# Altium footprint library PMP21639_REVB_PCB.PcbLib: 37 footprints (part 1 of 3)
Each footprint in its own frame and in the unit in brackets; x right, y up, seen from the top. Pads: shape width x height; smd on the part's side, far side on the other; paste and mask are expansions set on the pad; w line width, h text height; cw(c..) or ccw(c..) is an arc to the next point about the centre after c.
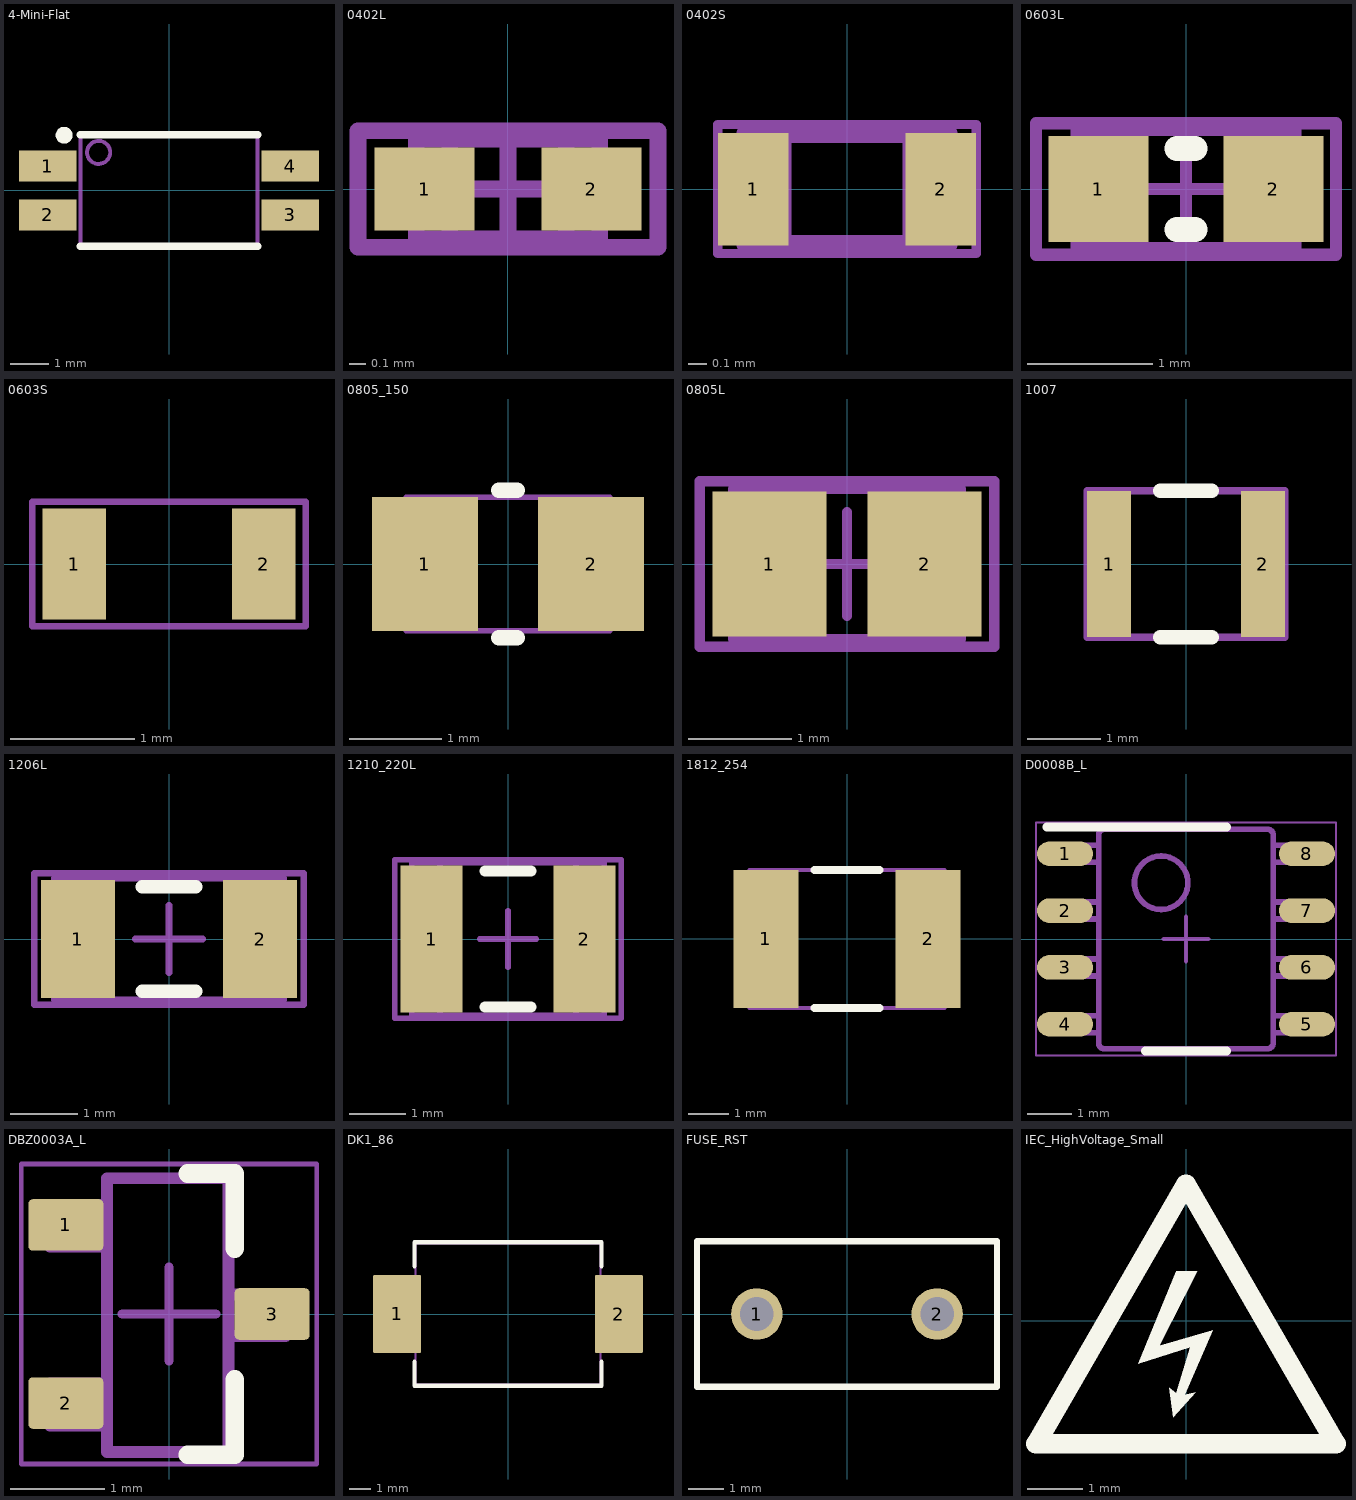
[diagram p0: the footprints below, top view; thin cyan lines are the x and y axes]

## 4-Mini-Flat [mm] "Sharp"
height 2.4
pads (4):
  rect 1.5x0.8 smd: 1(-3.15,0.635) 2(-3.15,-0.635) 3(3.15,-0.635) 4(3.15,0.635)
Top Overlay:
  circle w0.254: c-2.728,1.437 r0.091
  lines w0.2: -2.3,-1.45 2.3,-1.45 ; -2.3,1.45 2.3,1.45
Mechanical 5:
  circle w0.1: c-1.829,0.991 r0.3
  lines w0.1: -2.3,-1.45 2.3,-1.45 2.3,1.45 -2.3,1.45 -2.3,-1.45
  text ".Designator" at -1.88,-0.508 h1.02
3D body: height 2.4, standoff 0, extent -2.299,-1.449 2.3,1.45
3D body: height 2.41, standoff 2.4, extent -1.984,0.379 -1.386,0.978

## 0402L [mm] "0402 from SM-752 data"
height 0.6
pads (2):
  rect 0.6x0.5 smd: 1(-0.5,0) 2(0.5,0)
Mechanical 5:
  lines w0.1: -0.9,-0.35 0.9,-0.35 0.9,0.35 -0.9,0.35 -0.9,-0.35
  text ".Designator" at -0.775,-0.225 h0.43
Mechanical 13:
  lines w0.1: -0.35,-0.3 -0.35,0.3 ; 0.35,-0.3 0.35,0.3 ; -0.55,-0.3 -0.55,0.3 0.55,0.3 0.55,-0.3 -0.55,-0.3
Mechanical 15:
  lines w0.1: -0.3,0 0.3,0 ; 0,-0.3 0,0.3 ; -0.9,-0.35 -0.9,0.35 0.9,0.35 0.9,-0.35 -0.9,-0.35
3D body: height 0.6, standoff 0, extent -0.549,-0.299 -0.351,0.299
3D body: height 0.6, standoff 0, extent -0.349,-0.299 0.349,0.299
3D body: height 0.6, standoff 0, extent 0.351,-0.299 0.549,0.299

## 0402S [mil] "Based on C0402S footprint from PADS legacy"
height 23.62
pads (2):
  rect 15x24 smd: 1(-20,0) 2(20,0)
Mechanical 5:
  lines w1.97: -27.56,-13.78 27.56,-13.78 27.56,13.78 -27.56,13.78 -27.56,-13.78
  text ".Designator" at -21.65,-5.91 h12
Mechanical 13:
  lines w3.94: -13.78,-11.81 -13.78,11.81 ; 13.78,-11.81 13.78,11.81 ; -21.65,-11.81 -21.65,11.81 21.65,11.81 21.65,-11.81 -21.65,-11.81
3D body: height 23.62, standoff 0, extent -21.63,-11.79 -13.8,11.79
3D body: height 23.62, standoff 0, extent -13.76,-11.79 13.76,11.79
3D body: height 23.62, standoff 0, extent 13.8,-11.79 21.63,11.79

## 0603L [mm] "0603 from SM-752 data"
height 1
pads (2):
  rect 0.8x0.85 smd: 1(-0.7,0) 2(0.7,0)
Top Overlay:
  lines w0.2: -0.071,-0.325 0.071,-0.325 ; -0.071,0.325 0.071,0.325
Mechanical 5:
  lines w0.1: -1.2,-0.525 -1.2,0.525 1.2,0.525 1.2,-0.525 -1.2,-0.525
  text ".Designator" at -1.05,-0.275 h0.56
Mechanical 13:
  lines w0.1: -0.55,-0.475 -0.55,0.475 ; 0.55,-0.475 0.55,0.475 ; -0.875,-0.475 -0.875,0.475 0.875,0.475 0.875,-0.475 -0.875,-0.475
Mechanical 15:
  lines w0.1: -0.475,0 0.475,0 ; 0,-0.475 0,0.475 ; -1.2,-0.525 1.2,-0.525 1.2,0.525 -1.2,0.525 -1.2,-0.525
3D body: height 1, standoff 0, extent 0.551,-0.474 0.874,0.474
3D body: height 1, standoff 0, extent -0.549,-0.474 0.549,0.474
3D body: height 1, standoff 0, extent -0.874,-0.474 -0.551,0.474

## 0603S [mil]
height 39.37
pads (2):
  rect 20x35 smd: 1(-30,0) 2(30,0)
Mechanical 5:
  lines w1.97: -43.31,-19.68 43.31,-19.68 43.31,19.68 -43.31,19.68 -43.31,-19.68
  text ".Designator" at -32.48,-8.86 h18
3D body: height 39.37, standoff 0, extent -34.43,-18.68 -21.67,18.68
3D body: height 39.37, standoff 0, extent -21.63,-18.68 21.63,18.68
3D body: height 39.37, standoff 0, extent 21.67,-18.68 34.43,18.68

## 0805_150 [mm] "0805 / 1.5 mm height"
height 1.5
pads (2):
  rect 1.15x1.45 smd: 1(-0.9,0) 2(0.9,0)
Top Overlay:
  lines w0.17: -0.1,-0.8 0.1,-0.8 ; -0.1,0.8 0.1,0.8
Mechanical 5:
  lines w0.06: -1.1,-0.725 1.1,-0.725 1.1,0.725 -1.1,0.725 -1.1,-0.725
  text ".Designator" at -0.975,-0.3 h0.53
3D body: height 1.5, standoff 0, extent -1.099,-0.724 -0.501,0.724
3D body: height 1.5, standoff 0, extent -0.499,-0.724 0.5,0.725
3D body: height 1.5, standoff 0, extent 0.501,-0.724 1.099,0.724

## 0805L [mm] "0805 from SM-752 data"
height 1.45
pads (2):
  rect 1.1x1.4 smd: 1(-0.75,0) 2(0.75,0)
Mechanical 5:
  lines w0.1: -1.425,-0.8 1.425,-0.8 1.425,0.8 -1.425,0.8 -1.425,-0.8
  text ".Designator" at -1.2,-0.325 h0.64
Mechanical 13:
  lines w0.1: -0.65,-0.725 -0.65,0.725 ; 0.65,-0.725 0.65,0.725 ; -1.1,-0.725 -1.1,0.725 1.1,0.725 1.1,-0.725 -1.1,-0.725
Mechanical 15:
  lines w0.1: -0.5,0 0.5,0 ; 0,-0.5 0,0.5 ; -1.425,-0.8 -1.425,0.8 1.425,0.8 1.425,-0.8 -1.425,-0.8
3D body: height 1.45, standoff 0, extent 0.651,-0.724 1.099,0.724
3D body: height 1.45, standoff 0, extent -0.649,-0.724 0.649,0.724
3D body: height 1.45, standoff 0, extent -1.099,-0.724 -0.651,0.724

## 1007 [mm] "SMD, 2-Leads, Body 2.5x1.8mm"
height 2
pads (2):
  rect 0.6x2 smd: 1(-1.05,0) 2(1.05,0)
Top Overlay:
  lines w0.2: -0.35,-1 0.35,-1 ; -0.35,1 0.35,1
Mechanical 5:
  lines w0.1: -1.35,-1 1.35,-1 1.35,1 -1.35,1 -1.35,-1
  text ".Designator" at -1.1,-0.2 h0.6
3D body: height 2, standoff 0, extent 0.85,-1 1.35,1
3D body: height 2, standoff 0, extent -1.35,-1 -0.85,1
3D body: height 2, standoff 0, extent -0.85,-1 0.85,1

## 1206L [mm] "1206 from SM-752 data"
height 1.35
pads (2):
  rect 1.1x1.75 smd: 1(-1.35,0) 2(1.35,0)
Top Overlay:
  lines w0.2: -0.4,-0.775 0.4,-0.775 ; -0.4,0.775 0.4,0.775
Mechanical 5:
  lines w0.1: -1.7,-0.9 1.7,-0.9 1.7,0.9 -1.7,0.9 -1.7,-0.9
  text ".Designator" at -1.475,-0.4 h0.81
Mechanical 13:
  lines w0.1: -1.2,-0.9 -1.2,0.9 ; 1.2,-0.9 1.2,0.9 ; -1.7,-0.9 -1.7,0.9 1.7,0.9 1.7,-0.9 -1.7,-0.9
Mechanical 15:
  lines w0.1: -0.5,0 0.5,0 ; 0,-0.5 0,0.5 ; -2,-0.975 2,-0.975 2,0.975 -2,0.975 -2,-0.975
3D body: height 1.35, standoff 0, extent 1.201,-0.899 1.699,0.899
3D body: height 1.35, standoff 0, extent -1.199,-0.899 1.199,0.899
3D body: height 1.35, standoff 0, extent -1.699,-0.899 -1.201,0.899

## 1210_220L [mm] "1210"
height 2.2
pads (2):
  rect 1.1x2.6 smd: 1(-1.35,0) 2(1.35,0)
Top Overlay:
  lines w0.2: -0.4,-1.2 0.4,-1.2 ; -0.4,1.2 0.4,1.2
Mechanical 5:
  lines w0.1: -1.7,-1.35 -1.7,1.35 1.7,1.35 1.7,-1.35 -1.7,-1.35
  text ".Designator" at -1.4,-0.375 h0.76
Mechanical 13:
  lines w0.1: -1.2,-1.35 -1.2,1.35 ; 1.2,-1.35 1.2,1.35 ; -1.7,-1.35 -1.7,1.35 1.7,1.35 1.7,-1.35 -1.7,-1.35
Mechanical 15:
  lines w0.1: -0.5,0 0.5,0 ; 0,-0.5 0,0.5 ; -2,-1.4 2,-1.4 2,1.4 -2,1.4 -2,-1.4
3D body: height 2.2, standoff 0, extent -1.699,-1.349 -1.201,1.349
3D body: height 2.2, standoff 0, extent -1.199,-1.349 1.199,1.349
3D body: height 2.2, standoff 0, extent 1.201,-1.349 1.699,1.349

## 1812_254 [mm] "SMD, 2-Leads, Body 4.8x3.4mm"
height 2.54
pads (2):
  rect 1.6x3.4 smd: 1(-2,0) 2(2,0)
Top Overlay:
  lines w0.2: -0.8,-1.7 0.8,-1.7 ; -0.8,1.7 0.8,1.7
Mechanical 5:
  lines w0.1: -1.9,-1.7 -1.9,1.7 ; 1.9,-1.7 1.9,1.7 ; -2.4,-1.7 -2.4,1.7 2.4,1.7 2.4,-1.7 -2.4,-1.7
  text ".Designator" at -1.875,-0.5 h1.02
3D body: height 2.54, standoff 0, extent 1.901,-1.699 2.399,1.699
3D body: height 2.54, standoff 0, extent -1.899,-1.699 1.899,1.699
3D body: height 2.54, standoff 0, extent -2.399,-1.699 -1.901,1.699

## D0008B_L [mm] "SOIC, 8-Leads, Body 4.9x3.9mm, Pitch 1.27mm, IPC High Density"
height 1.75
pads (8):
  oval 1.25x0.55 smd: 1(-2.7,1.905) 2(-2.7,0.635) 3(-2.7,-0.635) 4(-2.7,-1.905) 5(2.7,-1.905) 6(2.7,-0.635) 7(2.7,0.635) 8(2.7,1.905)
Top Overlay:
  lines w0.2: -3.1,2.5 0.9,2.5 ; -0.9,-2.5 0.9,-2.5
Mechanical 5:
  lines w0.127: -2.375,-2.095 -1.995,-2.095 -1.952,-2.095 -1.952,-1.715 -1.995,-1.715 -2.375,-1.715 ; -2.375,-2.095 -2.589,-2.095 -3.002,-2.095 -3.002,-1.715 -2.589,-1.715 -2.375,-1.715 ; -2.375,-2.095 -2.375,-1.715 ; -2.375,-0.825 -1.995,-0.825 -1.952,-0.825 -1.952,-0.445 -1.995,-0.445 -2.375,-0.445 ; -2.375,-0.825 -2.589,-0.825 -3.002,-0.825 -3.002,-0.445 -2.589,-0.445 -2.375,-0.445 ; -2.375,-0.825 -2.375,-0.445 ; -2.375,0.445 -1.995,0.445 -1.952,0.445 -1.952,0.825 -1.995,0.825 -2.375,0.825 ; -2.375,0.445 -2.589,0.445 -3.002,0.445 -3.002,0.825 -2.589,0.825 -2.375,0.825 ; -2.375,0.445 -2.375,0.825 ; -2.375,1.715 -1.995,1.715 -1.952,1.715 -1.952,2.095 -1.995,2.095 -2.375,2.095 ; -2.375,1.715 -2.589,1.715 -3.002,1.715 -3.002,2.095 -2.589,2.095 -2.375,2.095 ; -2.375,1.715 -2.375,2.095 ; -0.332,-2.45 -1.825,-2.45 -1.826,-2.45 cw(c-1.825,-2.323) -1.952,-2.324 -1.952,-2.323 -1.952,2.323 -1.952,2.324 cw(c-1.825,2.323) -1.826,2.45 -1.825,2.45 -0.332,2.45 ; -0.332,-2.45 -0.182,-2.45 ; -0.332,-2.45 -0.182,-2.45 ; -0.332,2.45 -0.182,2.45 ; -0.332,2.45 -0.182,2.45 ; -0.182,-2.45 0.178,-2.45 ; -0.182,2.45 0.178,2.45 ; 0.178,-2.45 0.328,-2.45 ; 0.178,-2.45 0.328,-2.45 ; 0.178,2.45 0.328,2.45 ; 0.178,2.45 0.328,2.45 ; 0.328,-2.45 1.821,-2.45 1.822,-2.45 ccw(c1.821,-2.323) 1.948,-2.324 1.948,-2.323 1.948,2.323 1.948,2.324 ccw(c1.821,2.323) 1.822,2.45 1.821,2.45 0.328,2.45 ; 2.371,-2.095 2.585,-2.095 2.998,-2.095 2.998,-1.715 2.585,-1.715 2.371,-1.715 ; 2.371,-2.095 1.991,-2.095 1.948,-2.095 1.948,-1.715 1.991,-1.715 2.371,-1.715 ; 2.371,-2.095 2.371,-1.715 ; 2.371,-0.825 2.585,-0.825 2.998,-0.825 2.998,-0.445 2.585,-0.445 2.371,-0.445 ; 2.371,-0.825 1.991,-0.825 1.948,-0.825 1.948,-0.445 1.991,-0.445 2.371,-0.445 ; 2.371,-0.825 2.371,-0.445 ; 2.371,0.445 2.585,0.445 2.998,0.445 2.998,0.825 2.585,0.825 2.371,0.825 ; 2.371,0.445 1.991,0.445 1.948,0.445 1.948,0.825 1.991,0.825 2.371,0.825 ; 2.371,0.445 2.371,0.825 ; 2.371,1.715 2.585,1.715 2.998,1.715 2.998,2.095 2.585,2.095 2.371,2.095 ; 2.371,1.715 1.991,1.715 1.948,1.715 1.948,2.095 1.991,2.095 2.371,2.095 ; 2.371,1.715 2.371,2.095 ; -0.555,0.659 cw(c-0.555,1.256) -0.555,1.853 cw(c-0.555,1.256) -0.555,0.659
  text ".Designator" at -1.625,-0.625 h0.89
Mechanical 15:
  lines w0.05: -3.35,-2.6 -3.35,2.6 3.35,2.6 3.35,-2.6 -3.35,-2.6
  lines w0.1: -0.5,0 0.5,0 ; 0,-0.5 0,0.5
3D body "D0008A.stp": height 1.63, standoff 0, extent -3,-2.45 3,2.45

## DBZ0003A_L [mm] "SOT23, 3-Leads, Body 2.9x1.3mm, Pitch 0.95mm, Lead Span 2.4mm, IPC High Density"
height 1.12
pads (3):
  rrect18% 0.8x0.55 smd: 1(-1.1,0.95) 2(-1.1,-0.95) 3(1.1,0)
Top Overlay:
  lines w0.2: 0.2,-1.5 0.7,-1.5 0.7,-0.7 ; 0.2,1.5 0.7,1.5 0.7,0.7
Mechanical 5:
  lines w0.127: -1.27,-1.187 -1.27,-0.743 -1.063,-0.743 -1.005,-0.743 -0.814,-0.743 -0.66,-0.743 -0.66,-1.187 -0.814,-1.187 -1.005,-1.187 -1.063,-1.187 -1.27,-1.187 ; -1.27,0.718 -1.27,1.162 -1.063,1.162 -1.005,1.162 -0.814,1.162 -0.66,1.162 -0.66,0.718 -0.814,0.718 -1.005,0.718 -1.063,0.718 -1.27,0.718 ; -0.66,-1.473 -0.66,1.448 0.635,1.448 0.635,-1.473 -0.66,-1.473 ; 0.635,-0.235 0.789,-0.235 0.98,-0.235 1.037,-0.235 1.245,-0.235 1.245,0.21 1.037,0.21 0.98,0.21 0.789,0.21 0.635,0.21 0.635,-0.235
  text ".Designator" at -0.254,0.889 h0.51
Mechanical 15:
  lines w0.05: -1.575,-1.6 -1.575,1.6 1.575,1.6 1.575,-1.6 -1.575,-1.6
  lines w0.1: -0.5,0 0.5,0 ; 0,-0.5 0,0.5
3D body "DBZ0003A.stp": height 0.98, standoff 0, extent -1.257,-1.46 1.257,1.461

## DK1_86 [mm] "SMD, 2-Leads, Body 8x6mm"
height 2.5
pads (2):
  rrect5% 2.2x3.6 smd: 1(-5.1,0) 2(5.1,0)
Top Overlay:
  lines w0.2: -4.3,-2.2 -4.3,-3.3 4.3,-3.3 4.3,-2.2 ; -4.3,2.2 -4.3,3.3 4.3,3.3 4.3,2.2
Mechanical 5:
  lines w0.1: -4.25,-1.4 -5.95,-1.4 -5.95,1.4 -4.25,1.4 ; 4.25,-1.4 5.95,-1.4 5.95,1.4 4.25,1.4 ; -4.25,-3.25 -4.25,3.25 4.25,3.25 4.25,-3.25 -4.25,-3.25
  text ".Designator" at -2.6,-0.5 h1.52
3D body: height 2.5, standoff 0, extent -4.25,-3.25 4.25,3.25
3D body: height 0.2, standoff 0, extent -5.95,-1.4 -4.25,1.4
3D body: height 0.2, standoff 0, extent 4.25,-1.4 5.95,1.4

## FUSE_RST [mm] "Bel Fuse RST series May2012D"
height 7.9
pads (2):
  round 1.45 hole 0.95: 1(-2.54,0) 2(2.54,0)
Top Overlay:
  lines w0.178: -4.225,-2.05 4.225,-2.05 4.225,2.05 -4.225,2.05 -4.225,-2.05
Mechanical 5:
  lines w0.1: -4.225,-2.05 -4.225,2.05 4.225,2.05 4.225,-2.05 -4.225,-2.05
  text ".Designator" at -0.498,-0.503 h0.6
3D body "Fuse_RST.stp": height 7.9, standoff -4.3, extent -4.225,-2.05 4.225,2.05

## IEC_HighVoltage_Small [mm]
Top Overlay:
  region: -0.178,0.889 0.203,0.889 -0.483,-0.457 0.483,-0.178 -0.025,-1.346 0.178,-1.295 -0.229,-1.753 -0.305,-1.219 -0.178,-1.321 0.076,-0.483 -0.864,-0.787
  lines w0.356: -2.718,-2.235 2.718,-2.235 0,2.472 -2.718,-2.235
